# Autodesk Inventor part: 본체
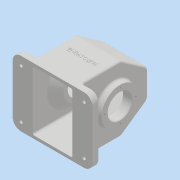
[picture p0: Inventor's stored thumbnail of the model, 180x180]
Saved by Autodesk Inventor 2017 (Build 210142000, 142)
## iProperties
Part Number: 본체
Material: 일반
Document SubType Name: Modeling
Designer: MRC
Density: 1 g/cm^3
Appearance: 기본값
Author: MRC
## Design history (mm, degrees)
sketch "스케치1"
  geometry: L1 (-65, -55)-(12, -55); L2 (12, -55)-(57, -23.491); L3 (57, -23.491)-(57, 23.491); L4 (57, 23.491)-(12, 55); L5 (12, 55)-(-65, 55); L6 (-65, 55)-(-65, -55); 3 further points
  constraints: 12 end point, 2 horizontal alignment, 2 midpoint, 2 perpendicular, 1 horizontal, 1 parallel
  dimensions: "d0" = 65 distance from line of L6 point (0, 0); "d1" = 77 distance of L1.start L1.end; "d2" = 35 deg angle of L1 L2; "d3" = 35 deg angle of L5 L4; "d4" = 110 distance of L5.end L1.start; "d5" = 122 distance between parallel lines of L6 L3
extrude "돌출1" new body sketch "스케치1" stored distance "d6" = 77; taper "d7" = 0 deg
feature "쉘1" dims "d8" = 5
sketch "스케치2"
  geometry: L1 (0, 0)-(0, 110) reference; L2 (0, 110)-(-28.5, 110); L3 (-28.5, 110)-(-28.5, 0); L4 (-28.5, 0)-(0, 0); 1 further point
  constraints: 6 end point, 2 horizontal, 1 perpendicular
  dimensions: "d9" = 67 distance from line of point (38.5, 55) L3
extrude "돌출2" join sketch "스케치2" distance "d10" = 12; taper "d11" = 0 deg
sketch "스케치3"
  geometry: C1 r 37.5 at (0, 0); 1 further point
  constraints: 1 centre point, 1 coincident
  dimensions: "d12" = 75 diameter of C1
extrude "돌출3" join sketch "스케치3" distance "d13" = 5; taper "d14" = 0 deg
sketch "스케치5"
  geometry: C1 r 31 at (0, 0); 1 further point
  constraints: 1 centre point, 1 coincident
  dimensions: "d24" = 62 diameter of C1
extrude "돌출4" join sketch "스케치5" distance "d25" = 10; taper "d26" = 0 deg
node "작업 평면1"
sketch "스케치6"
  geometry: C1 r 27 at (0, 0); 1 further point
  constraints: 1 centre point, 1 coincident
  dimensions: "d28" = 54 diameter of C1
extrude "돌출5" join sketch "스케치6" stored distance "d29" = 10; taper "d30" = 45 deg
hole "구멍2" diameter "d33" = 40; stored, may be unused: countersink angle "d37" = 90 deg, drill point angle "d39" = 118 deg; dims "d31" = 10, "d32" = 10, "d34" = 6, "d35" = 4, "d36" = 2, "d38" = 24
hole "구멍3" diameter "d42" = 40; stored, may be unused: countersink angle "d46" = 90 deg, drill point angle "d48" = 118 deg; dims "d40" = 10, "d41" = 10, "d43" = 6, "d44" = 4, "d45" = 2, "d47" = 15
sketch "스케치7"
  geometry: C1 r 6 at (38.5, 23.491); 1 further point
  constraints: 1 centre point, 1 coincident
  dimensions: "d49" = 12 diameter of C1
extrude "돌출6" join sketch "스케치7" distance "d50" = 4; taper "d51" = 0 deg
sketch "스케치8"
  geometry: A1 r 29 centre (0, 0) between (0, 29) and (29, 0); 3 further points
  constraints: 4 point on circle, 2 horizontal alignment, 2 vertical alignment, 1 centre point, 1 coincident
  dimensions: "d52" = 58 diameter of A1
hole "구멍4" sketch "스케치8" at (0, 29), (29, 0), (0, -29), (-29, 0) diameter "d53" = 2.459; stored, may be unused: countersink angle "d57" = 90 deg, drill point angle "d59" = 118 deg; dims "d54" = 6, "d55" = 4, "d56" = 2, "d58" = 8
sketch "스케치9"
  geometry: A1 r 26 centre (0, 0) between (0, 26) and (26, 0); 3 further points
  constraints: 4 point on circle, 2 horizontal alignment, 2 vertical alignment, 1 centre point, 1 coincident
  dimensions: "d60" = 52 diameter of A1
hole "구멍5" sketch "스케치9" at (0, 26), (26, 0), (0, -26), (-26, 0) diameter "d61" = 2.459; stored, may be unused: countersink angle "d65" = 90 deg, drill point angle "d67" = 118 deg; dims "d62" = 6, "d63" = 4, "d64" = 2, "d66" = 8.8
hole "구멍6" diameter "d70" = 5.188; stored, may be unused: countersink angle "d74" = 90 deg, drill point angle "d76" = 118 deg; dims "d68" = 10, "d69" = 10, "d71" = 12, "d72" = 4, "d73" = 2, "d75" = 31
fillet "모깎기1" dims "d77" = 10
fillet "모깎기8" dims "d92" = 14
sketch "스케치11"
  geometry: L1 (-28.5, -96)-(-28.5, -14) reference; L2 (5, -5)-(5, -105) reference; L3 (5, -105)-(72, -105) reference; L4 (72, -105)-(72, -5) reference; L5 (72, -5)-(5, -5) reference; L6 (-28.5, -96)-(-28.5, -14) reference; L7 (91.5, 0)-(-14.5, 0) reference; L8 (105.5, -96)-(105.5, -14) reference; L9 (-14.5, -110)-(91.5, -110) reference; A1 r 14 centre (-14.5, -14) between (-14.5, 0) and (-28.5, -14) reference; A2 r 14 centre (-14.5, -96) between (-28.5, -96) and (-14.5, -110) reference; A3 r 14 centre (-14.5, -96) between (-28.5, -96) and (-14.5, -110) reference; A4 r 14 centre (-14.5, -14) between (-14.5, 0) and (-28.5, -14) reference; A5 r 14 centre (91.5, -14) between (105.5, -14) and (91.5, 0) reference; A6 r 14 centre (91.5, -96) between (91.5, -110) and (105.5, -96) reference; 5 further points
  constraints: 4 coincident
hole "구멍7" sketch "스케치11" at (-14.5, -14), (-14.5, -96), (91.5, -96), (91.5, -14) diameter "d93" = 5.5; stored, may be unused: countersink angle "d97" = 90 deg, drill point angle "d99" = 118 deg; dims "d94" = 12, "d95" = 15, "d96" = 2, "d98" = 31
fillet "모깎기4" dims "d80" = 3
chamfer "모따기1" distance "d81" = 1; stored, may be unused: second distance "d82" = 2, angle "d83" = 45 deg
fillet "모깎기5" dims "d84" = 3
fillet "모깎기6" dims "d85" = 3
fillet "모깎기7" dims "d86" = 3
fillet "모깎기9" dims "d101" = 3
node "작업 평면5"
sketch "스케치13" dims "d0" = 65, "d1" = 77, "d2" = 35 deg, "d3" = 35 deg, "d4" = 110, "d5" = 122
  geometry: L1 (14.5, 73.847)-(14.5, 15) reference; L2 (0, 0)-(106, 0) reference; 2 further points
  constraints: 1 other
  dimensions: "d103" = 38.5 distance from line of point (53, 50) L1; "d104" = 50 distance from line of point (53, 50) L2
feature "엠보싱2" sketch "스케치13" dims "d105" = 0.5, "d106" = 0
node "솔리드1"
mirror "미러1"
node "투영된 루프1"
other parameters: "d27" = -24
